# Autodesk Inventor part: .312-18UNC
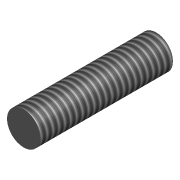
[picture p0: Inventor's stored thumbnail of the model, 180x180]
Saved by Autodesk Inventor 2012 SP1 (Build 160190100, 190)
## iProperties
Shininess: 0.0
Length Units: 11269
Angle Units: 11279
Time Units: 11290
Mass Units: 11283
Length Display Precision: 3
Angle Display Precision: 2
Compacted: True
Created: 2000-10
Part Number: .312-18UNC
Description: ALL THREAD 1.25" LONG
Document SubType Name: Modeling
Designer: Ron
Density: 1 g/cm^3
Material: Default
Density: 0.0
Volumn: 0.0
Area: 0.0
PropertySet Name: Model Information
Control State: 0
Master: False
Checked Out: False
Author: Ron
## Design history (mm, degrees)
node "Extrusion1" dims "d1" = 31.75, "d2" = 0
  sketch "Sketch1"
    geometry: L1 (116.168, -329.148)-(116.078, -316.448) reference; L2 (119.545, -329.148)-(116.168, -329.148) reference; L3 (119.635, -316.448)-(119.545, -329.148) reference; L4 (119.635, 318.152)-(119.635, -316.448) reference; L5 (119.545, 330.852)-(119.635, 318.152) reference; L6 (116.168, 330.852)-(119.545, 330.852) reference; L7 (116.078, 318.152)-(116.168, 330.852) reference; L8 (116.078, -316.448)-(116.078, 318.152) reference; C1 r 3.969 at (0, 0); 27 further points; 26 other entities
    constraints: 1 centre point, 1 coincident, 26 other
    dimensions: "d0" = 7.9375 diameter of C1
thread "Thread1" dims "d3" = 10, "d4" = 0
body "Solid1"
node "Reference1"
